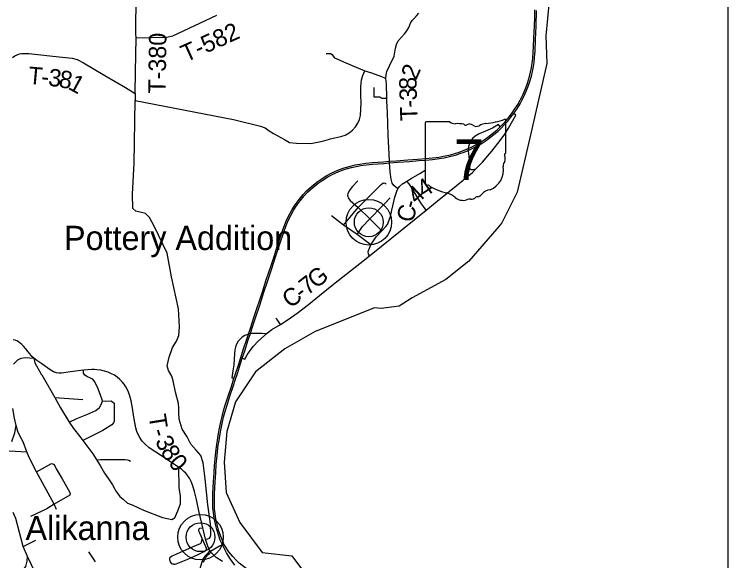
# Model space of a CAD drawing. Extents: x 2402298 to 2498138, y 789485 to 950881.
# Drawn here: x 2484526 to 2496836, y 874577 to 883995 of the extents above; entities that cross this region are included whole.
import ezdxf

# ---------------------------------------------------------------- set-up
doc = ezdxf.new("R2010")
doc.units = 0
for name, color, linetype in [('GM_X_County', 7, 'Continuous'), ('GM_X_County_Road', 7, 'Continuous'), ('GM_X_County_Road_Text', 7, 'Continuous'), ('GM_X_Interchange_Ramps', 7, 'Continuous'), ('GM_X_State_Route', 7, 'Continuous'), ('GM_X_State_Shield', 7, 'Continuous'), ('GM_X_Township', 7, 'Continuous'), ('GM_X_Township_Road', 7, 'Continuous'), ('GM_X_Township_Road_Text', 7, 'Continuous'), ('GM_X_Unincorporated', 7, 'Continuous'), ('GM_X_Unincorporated_Text', 7, 'Continuous'), ('SH_Text', 7, 'Continuous')]:
    doc.layers.add(name, color=color, linetype=linetype)

msp = doc.modelspace()

# ---------------------------------------------------------------- linework, layer by layer
at = {"layer": 'GM_X_County'}
msp.add_lwpolyline([(2493786, 884527), (2493696, 883623), (2493714, 883148), (2493437, 881943), (2493206, 880930), (2492937, 880401), (2492855, 880298), (2492372, 879737), (2491970, 879426), (2491391, 879109), (2491168, 878963), (2490858, 878924), (2490743, 878938), (2489719, 878525), (2489193, 878228), (2488688, 877835), (2488342, 877317), (2488195, 876804), (2488146, 876274), (2488182, 875754), (2488416, 875238), (2488804, 874720), (2489314, 874658), (2489689, 874158)], dxfattribs=at)
at = {"layer": 'GM_X_County_Road'}
for points in [[(2491237, 881079), (2491301, 881119), (2491373, 881162), (2491526, 881251), (2491618, 881307)], [(2488871, 878489), (2488973, 878560), (2489117, 878650), (2489235, 878722), (2489410, 878841), (2489600, 878990), (2489794, 879147), (2490037, 879345), (2490491, 879697), (2490658, 879833), (2491632, 880617), (2491825, 880776), (2492030, 880942), (2492270, 881138), (2492309, 881177), (2492339, 881221)], [(2490658, 879833), (2490637, 879861), (2490631, 879907), (2490679, 880023), (2490772, 880157), (2490870, 880265), (2490940, 880337), (2490964, 880369), (2490978, 880401), (2491015, 880509), (2491043, 880616), (2491090, 880843), (2491126, 880945), (2491146, 880986), (2491173, 881024), (2491233, 881077), (2491237, 881079)], [(2488120, 874563), (2488012, 874634), (2487946, 874695), (2487920, 874726), (2487913, 874734)]]:
    msp.add_lwpolyline(points, dxfattribs=at)
at = {"layer": 'GM_X_Interchange_Ramps'}
for points in [[(2492339, 881221), (2492370, 881219), (2492430, 881270), (2492478, 881320), (2492603, 881445), (2492698, 881553), (2492768, 881636), (2492911, 881820), (2492988, 881926), (2493053, 882033), (2493127, 882165), (2493179, 882259), (2493144, 882284)], [(2492911, 882058), (2492884, 882093), (2492779, 882035), (2492655, 881981), (2492546, 881933), (2492478, 881894), (2492434, 881853), (2492399, 881808), (2492378, 881762), (2492366, 881717), (2492359, 881682), (2492358, 881650), (2492362, 881590), (2492368, 881543), (2492382, 881443), (2492385, 881392), (2492380, 881345), (2492377, 881322), (2492372, 881300), (2492362, 881272), (2492348, 881241), (2492339, 881221)], [(2492380, 881345), (2492395, 881329), (2492404, 881321), (2492424, 881317), (2492445, 881319), (2492467, 881328), (2492478, 881320)], [(2488871, 878489), (2488805, 878493), (2488642, 878493), (2488601, 878491), (2488568, 878484), (2488503, 878460), (2488457, 878431), (2488422, 878398), (2488391, 878358), (2488363, 878308), (2488345, 878258), (2488334, 878212), (2488326, 878147), (2488312, 877955), (2488299, 877850), (2488278, 877731), (2488316, 877716)], [(2488461, 878069), (2488502, 878053), (2488544, 878125), (2488583, 878184), (2488647, 878268), (2488738, 878366), (2488840, 878453), (2488871, 878489)], [(2487901, 874750), (2487886, 874731), (2487868, 874708), (2487846, 874690), (2487825, 874669), (2487803, 874638), (2487782, 874601), (2487762, 874553), (2487721, 874420), (2487707, 874379), (2487675, 874290), (2487640, 874219), (2487598, 874147), (2487544, 874073), (2487499, 874019), (2487462, 873981), (2487487, 873946)], [(2487789, 874549), (2487806, 874590), (2487824, 874624), (2487841, 874650), (2487864, 874676), (2487901, 874708), (2487920, 874726)]]:
    msp.add_lwpolyline(points, dxfattribs=at)
at = {"layer": 'GM_X_State_Route'}
msp.add_line((2487913, 874734), (2487901, 874750), dxfattribs=at)
for points in [[(2488331, 874497), (2488256, 874603), (2488189, 874712), (2488117, 874849), (2488080, 874931), (2488054, 875004), (2488022, 875112), (2487998, 875206), (2487976, 875314), (2487964, 875399), (2487954, 875485), (2487952, 875620), (2487954, 875741), (2487966, 875937), (2487975, 876098), (2487983, 876218), (2487992, 876335), (2488004, 876453), (2488019, 876580), (2488049, 876772), (2488066, 876864), (2488090, 876970), (2488113, 877061), (2488138, 877161), (2488161, 877240), (2488223, 877430), (2488272, 877582), (2488316, 877716), (2488350, 877817), (2488387, 877930), (2488435, 878080), (2488484, 878228), (2488533, 878378), (2488568, 878484), (2488601, 878583), (2488662, 878771), (2488712, 878923), (2488762, 879074), (2488813, 879228), (2488874, 879416), (2488913, 879535), (2488963, 879685), (2489014, 879839), (2489062, 879990), (2489100, 880105), (2489153, 880260), (2489195, 880373), (2489226, 880447), (2489278, 880556), (2489319, 880628), (2489359, 880691), (2489391, 880736), (2489439, 880802), (2489513, 880890), (2489571, 880951), (2489652, 881026), (2489745, 881101), (2489819, 881154), (2489918, 881215), (2489993, 881254), (2490060, 881287), (2490137, 881319), (2490218, 881349), (2490326, 881380), (2490407, 881398), (2490491, 881413), (2490592, 881427), (2490703, 881438), (2490898, 881453), (2491001, 881461), (2491117, 881470), (2491315, 881486), (2491486, 881499), (2491629, 881511), (2491740, 881521), (2491851, 881535), (2491933, 881549), (2492051, 881574), (2492129, 881596), (2492202, 881619), (2492277, 881647), (2492359, 881682), (2492422, 881711), (2492493, 881749), (2492562, 881788), (2492631, 881832), (2492699, 881878), (2492777, 881938), (2492856, 882006), (2492911, 882058), (2492962, 882108), (2493016, 882167), (2493071, 882234), (2493119, 882298), (2493153, 882346), (2493214, 882443), (2493255, 882515), (2493308, 882620), (2493354, 882730), (2493383, 882809), (2493417, 882920), (2493435, 882997), (2493451, 883075), (2493464, 883153), (2493473, 883235), (2493482, 883350), (2493487, 883434), (2493493, 883591), (2493500, 883790), (2493506, 883946), (2493510, 884073)], [(2492358, 881650), (2492439, 881688), (2492511, 881726), (2492580, 881765), (2492649, 881809), (2492714, 881855), (2492779, 881904), (2492873, 881983), (2492928, 882035), (2492987, 882094), (2493040, 882153), (2493095, 882220), (2493144, 882284), (2493208, 882379), (2493253, 882454), (2493291, 882521), (2493342, 882627), (2493387, 882737), (2493421, 882834), (2493448, 882929), (2493467, 883008), (2493483, 883096), (2493494, 883166), (2493504, 883254), (2493512, 883362), (2493519, 883558), (2493529, 883788), (2493539, 884061)], [(2488053, 876612), (2488077, 876766), (2488095, 876858), (2488119, 876969), (2488138, 877052), (2488165, 877150), (2488191, 877241), (2488252, 877430), (2488301, 877577), (2488342, 877706), (2488376, 877806), (2488413, 877919), (2488461, 878069), (2488503, 878196), (2488564, 878382), (2488601, 878491), (2488628, 878573), (2488689, 878762), (2488762, 878983), (2488834, 879204), (2488894, 879388), (2488968, 879611), (2489041, 879834), (2489103, 880020), (2489176, 880242), (2489216, 880352), (2489254, 880442), (2489301, 880538), (2489344, 880615), (2489377, 880668), (2489408, 880713), (2489457, 880779), (2489530, 880867), (2489588, 880928), (2489677, 881010), (2489767, 881084), (2489837, 881131), (2489936, 881192), (2490010, 881231), (2490077, 881264), (2490155, 881296), (2490235, 881324), (2490346, 881356), (2490425, 881373), (2490507, 881387), (2490602, 881400), (2490709, 881410), (2490902, 881426), (2491002, 881432), (2491147, 881445), (2491344, 881460), (2491504, 881473), (2491625, 881482), (2491743, 881494), (2491825, 881503), (2491942, 881522), (2492059, 881548), (2492138, 881569), (2492215, 881594), (2492286, 881620), (2492358, 881650)], [(2485718, 877860), (2485494, 877830), (2485342, 877808), (2485296, 877808), (2485253, 877813), (2485204, 877832), (2485147, 877868), (2484999, 877969), (2484916, 878028), (2484865, 878069), (2484832, 878099), (2484793, 878142), (2484766, 878177), (2484725, 878229), (2484684, 878275), (2484658, 878303), (2484629, 878329), (2484600, 878349), (2484571, 878366), (2484540, 878377), (2484509, 878385)], [(2487794, 875096), (2487782, 875146), (2487712, 875439), (2487668, 875634), (2487637, 875769), (2487609, 875867), (2487581, 875943), (2487551, 875998), (2487521, 876042), (2487487, 876083), (2487454, 876115), (2487414, 876152), (2487367, 876186), (2487205, 876294), (2486966, 876447), (2486856, 876522), (2486778, 876591), (2486734, 876640), (2486699, 876688), (2486665, 876750), (2486642, 876805), (2486623, 876865), (2486610, 876929), (2486588, 877050), (2486566, 877205), (2486541, 877335), (2486514, 877434), (2486483, 877511), (2486451, 877574), (2486421, 877620), (2486389, 877659), (2486347, 877701), (2486301, 877740), (2486253, 877772), (2486205, 877797), (2486146, 877824), (2486085, 877845), (2486017, 877862), (2485952, 877869), (2485908, 877872), (2485863, 877872), (2485718, 877860)], [(2487980, 875567), (2487979, 875613), (2487983, 875733), (2487994, 875930), (2488003, 876089), (2488012, 876239), (2488021, 876332), (2488033, 876457), (2488047, 876571), (2488053, 876612)], [(2487983, 875465), (2487982, 875476), (2487980, 875567)], [(2488143, 874860), (2488118, 874923), (2488092, 874992), (2488052, 875104), (2488027, 875198), (2488005, 875297), (2487990, 875389), (2487983, 875465)], [(2487901, 874750), (2487886, 874783), (2487862, 874843), (2487827, 874946), (2487794, 875096)], [(2488143, 874860), (2488117, 874849), (2488068, 874828), (2487913, 874734)], [(2488295, 874650), (2488230, 874730), (2488143, 874860)], [(2488900, 874171), (2488900, 874171), (2488837, 874242), (2488731, 874307), (2488600, 874392), (2488503, 874460), (2488408, 874537), (2488350, 874590), (2488302, 874642), (2488295, 874650)]]:
    msp.add_lwpolyline(points, dxfattribs=at)
at = {"layer": 'GM_X_State_Shield'}
for p, q in [((2493010, 881614), (2493010, 882167)), ((2491618, 882123), (2491618, 881066)), ((2492039, 882141), (2491631, 882141)), ((2493010, 881615), (2493010, 881614))]:
    msp.add_line(p, q, dxfattribs=at)
for centre, radius, start, end in [((2492514, 883581), 1476, 275.8445, 288.9065), ((2492994, 882169), 15.5, 351.8621, 97.738), ((2491634, 882125), 16.1, 98.1301, 188.1301), ((2492136, 882264), 156, 231.6195, 271.1119), ((2492188, 881548), 562, 80.4867, 94.9883), ((2492316, 882130), 45.1, 219.7921, 297.1024), ((2492382, 882008), 93.8, 54.4667, 119.1411), ((2492503, 882176), 113, 233.8562, 294.8282), ((2492702, 881818), 297, 97.3462, 120.7689), ((2493006, 881574), 24, 107.944, 210.337), ((2492854, 881504), 144, 340.033, 23.6496), ((2492993, 881612), 16.6, 289.6038, 7.7341), ((2493065, 881383), 105, 136.8065, 186.9296), ((2492597, 881313), 369, 292.3089, 8.9858), ((2491634, 881064), 16.3, 171.9584, 258.3066), ((2491636, 881172), 124, 267.339, 280.6039), ((2491662, 881005), 44.8, 29.7484, 93.2717), ((2492227, 881955), 1066, 240.4129, 257.1985), ((2492752, 880769), 202, 94.4031, 142.5768), ((2491909, 880591), 334, 47.1842, 75.836), ((2492270, 881000), 212, 230.7004, 286.2918), ((2492392, 880635), 174, 85.6951, 111.2099), ((2492408, 880921), 113, 268.777, 315.5493), ((2492510, 880818), 31.8, 65.7517, 132.6484), ((2492496, 880964), 119, 282.8732, 323.2771)]:
    msp.add_arc(centre, radius, start, end, dxfattribs=at)
at = {"layer": 'GM_X_Township'}
msp.add_lwpolyline([(2493786, 884527), (2493696, 883623), (2493714, 883148), (2493437, 881943), (2493206, 880930), (2492937, 880401), (2492855, 880298), (2492372, 879737), (2491970, 879426), (2491391, 879109), (2491168, 878963), (2490858, 878924), (2490743, 878938), (2489719, 878525), (2489193, 878228), (2488688, 877835), (2488342, 877317), (2488195, 876804), (2488146, 876274), (2488182, 875754), (2488416, 875238), (2488804, 874720), (2489314, 874658), (2489689, 874158)], dxfattribs=at)
at = {"layer": 'GM_X_Township_Road'}
for p, q in [((2490206, 883177), (2490577, 883019)), ((2486611, 882628), (2486618, 883003)), ((2485224, 877392), (2485709, 877354)), ((2484441, 876468), (2484743, 876451)), ((2485078, 875465), (2484809, 875337)), ((2484682, 874823), (2484896, 874928))]:
    msp.add_line(p, q, dxfattribs=at)
for points in [[(2486626, 883661), (2486624, 883739), (2486629, 884268), (2486628, 884307), (2486614, 884331), (2486593, 884347), (2486512, 884392), (2486479, 884423), (2486450, 884467), (2486015, 885223), (2485534, 885643), (2484538, 886597), (2484648, 886904), (2484650, 886910)], [(2491156, 883542), (2491209, 883603), (2491258, 883658), (2491297, 883710), (2491334, 883769), (2491360, 883844), (2491390, 883887), (2491422, 883918), (2491466, 883968), (2491506, 884013)], [(2486629, 883591), (2487153, 883601), (2487260, 883626), (2488024, 883978)], [(2486618, 883003), (2486629, 883591), (2486626, 883661)], [(2490940, 882886), (2490945, 882950), (2490956, 883009), (2490998, 883106), (2491080, 883273), (2491093, 883341), (2491106, 883411), (2491124, 883472), (2491152, 883538), (2491156, 883542)], [(2484493, 883248), (2484537, 883280), (2484575, 883297), (2484614, 883311), (2484658, 883317), (2484698, 883319), (2484778, 883317), (2485192, 883276), (2485526, 883236), (2485612, 883213), (2485723, 883158), (2486086, 882941), (2486443, 882731), (2486611, 882628)], [(2489905, 883321), (2489984, 883318), (2490012, 883302), (2490030, 883272), (2490052, 883245), (2490123, 883213), (2490206, 883177)], [(2489964, 881842), (2489979, 881846), (2490060, 881865), (2490158, 881886), (2490234, 881913), (2490306, 881949), (2490362, 881998), (2490412, 882054), (2490452, 882116), (2490481, 882182), (2490499, 882251), (2490510, 882466), (2490507, 882595), (2490508, 882679), (2490508, 882750), (2490512, 882807), (2490518, 882864), (2490542, 882939), (2490577, 883019), (2490689, 882985), (2490861, 882923), (2490912, 882902), (2490940, 882886)], [(2491146, 880986), (2491074, 881043), (2491049, 881084), (2491030, 881151), (2491014, 881281), (2491002, 881432), (2491001, 881461), (2490994, 881582), (2490978, 881912), (2490969, 882105), (2490965, 882303), (2490955, 882500), (2490952, 882549), (2490947, 882798), (2490940, 882886)], [(2490728, 882733), (2490728, 882574), (2490766, 882574)], [(2486611, 882628), (2486611, 882577), (2486613, 882509)], [(2490766, 882574), (2490831, 882572), (2490871, 882547), (2490952, 882549)], [(2487363, 877206), (2487359, 877288), (2487306, 877480), (2487268, 877677), (2487243, 877755), (2487188, 877853), (2487164, 877936), (2487199, 878083), (2487257, 878251), (2487328, 878361), (2487364, 878459), (2487377, 878607), (2487360, 878920), (2487240, 879469), (2487165, 879880), (2486939, 880341), (2486857, 880494), (2486788, 880561), (2486624, 880600), (2486570, 880647), (2486568, 880895), (2486596, 881430), (2486613, 882509)], [(2486613, 882509), (2488308, 882180), (2488777, 882065), (2488858, 882036), (2488927, 881987), (2488999, 881940), (2489186, 881836), (2489276, 881788), (2489394, 881774), (2489645, 881766), (2489843, 881810), (2489964, 881842)], [(2490453, 881123), (2490357, 881021), (2490303, 880953), (2490284, 880902), (2490278, 880879), (2490279, 880859)], [(2490803, 881009), (2490857, 881063), (2490883, 881083), (2490896, 881087), (2490911, 881088), (2490926, 881084), (2490945, 881074)], [(2491632, 880617), (2491586, 880680), (2491550, 880730), (2491502, 880811), (2491459, 880880), (2491384, 881001), (2491341, 881071), (2491301, 881119)], [(2490209, 880362), (2490460, 880662), (2490803, 881009)], [(2490279, 880859), (2490280, 880854), (2490286, 880830), (2490298, 880812), (2490319, 880788), (2490460, 880662), (2490662, 880467), (2490870, 880265)], [(2490873, 880685), (2490908, 880720), (2491012, 880832)], [(2490443, 880201), (2490535, 880336), (2490662, 880467), (2490873, 880685)], [(2490679, 880023), (2490443, 880201), (2490209, 880362), (2490000, 880522)], [(2489117, 878650), (2489097, 878683), (2489062, 878732), (2489040, 878757)], [(2484511, 877962), (2484545, 878000), (2484586, 878040), (2484644, 878065), (2484722, 878077), (2484865, 878069)], [(2484865, 878069), (2484880, 877990), (2484992, 877792)], [(2486046, 877334), (2486010, 877450), (2485965, 877567), (2485908, 877666), (2485880, 877707), (2485792, 877747), (2485741, 877772), (2485720, 877808), (2485718, 877860)], [(2484992, 877792), (2485000, 877779), (2485224, 877392), (2485326, 877214), (2485476, 876963), (2485546, 876858), (2485655, 876715), (2485710, 876646), (2485881, 876417), (2486006, 876220), (2486084, 876086), (2486150, 875990), (2486223, 875884), (2486264, 875811), (2486287, 875770)], [(2485476, 876963), (2485607, 877030), (2485780, 877096), (2485935, 877166), (2485999, 877219), (2486030, 877280), (2486046, 877334), (2486094, 877324), (2486194, 877330), (2486223, 877317), (2486247, 877294), (2486251, 877033), (2486247, 876982), (2486237, 876953), (2486212, 876921), (2486053, 876820), (2485710, 876646)], [(2484485, 876630), (2484535, 876779), (2484557, 876905), (2484533, 877034), (2484501, 877199)], [(2487827, 874946), (2487867, 874953), (2487892, 874967), (2487909, 874982), (2487914, 874998), (2487915, 875015), (2487912, 875213), (2487866, 875540), (2487819, 875986), (2487785, 876266), (2487747, 876392), (2487662, 876480), (2487571, 876584), (2487508, 876710), (2487423, 876842), (2487373, 877015), (2487366, 877135), (2487363, 877206)], [(2485253, 875460), (2485215, 875549), (2484907, 876107), (2484783, 876356), (2484743, 876451), (2484678, 876623), (2484629, 876719), (2484590, 876802), (2484557, 876905)], [(2484907, 876107), (2485167, 876252), (2485201, 876239), (2485227, 876210), (2485249, 876158), (2485350, 875988), (2485479, 875762), (2485488, 875734), (2485485, 875706), (2485215, 875549), (2485089, 875471), (2485078, 875465)], [(2485944, 876318), (2486012, 876319), (2486119, 876319), (2486373, 876321), (2486438, 876320), (2486480, 876316), (2486505, 876308), (2486534, 876293)], [(2487271, 875303), (2487299, 875317), (2487351, 875434), (2487395, 875559), (2487392, 875691), (2487370, 875837), (2487367, 876186)], [(2486287, 875770), (2486300, 875748), (2486347, 875685), (2486403, 875637), (2486478, 875569), (2486558, 875538), (2486756, 875448), (2487081, 875321), (2487242, 875288), (2487271, 875303)], [(2484962, 874217), (2484756, 874650), (2484682, 874823), (2484554, 875304), (2484505, 875407)], [(2487845, 874785), (2487830, 874815), (2487767, 874961), (2487710, 875092), (2487710, 875118), (2487729, 875135), (2487782, 875146)], [(2487221, 874644), (2487248, 874660), (2487277, 874672), (2487384, 874718), (2487602, 874818), (2487738, 874873), (2487750, 874883), (2487758, 874895), (2487764, 874924), (2487767, 874961)], [(2487277, 874515), (2487300, 874518), (2487320, 874524), (2487375, 874547), (2487523, 874605), (2487697, 874681), (2487801, 874733), (2487835, 874761), (2487845, 874785)], [(2484480, 874046), (2484486, 874162), (2484506, 874235), (2484562, 874311), (2484658, 874388), (2484723, 874478), (2484750, 874567), (2484756, 874650)], [(2485928, 874559), (2485815, 874727)], [(2487277, 874515), (2487260, 874518), (2487246, 874525), (2487233, 874540), (2487224, 874557), (2487213, 874591), (2487210, 874621), (2487214, 874635), (2487221, 874644)]]:
    msp.add_lwpolyline(points, dxfattribs=at)
at = {"layer": 'GM_X_Unincorporated'}
for centre, radius in [((2490643, 880411), 393), ((2490643, 880411), 249), ((2487739, 874982), 393), ((2487739, 874982), 249)]:
    msp.add_circle(centre, radius, dxfattribs=at)
at = {"layer": 'SH_Text'}
msp.add_lwpolyline([(2448187, 889729), (2496836, 889729), (2496836, 859271), (2448187, 859271)], close=True, dxfattribs=at)

# ---------------------------------------------------------------- texts
at = {"layer": 'GM_X_County_Road_Text'}
for s, rotation, p in [('4', 33.3056, (2491596, 880825)), ('4', 42.8256, (2491472, 880708)), ('C', 77.0088, (2491409, 880393)), ('-', 74.7437, (2491463, 880628)), ('G', 37.797, (2489730, 879254)), ('7', 37.7939, (2489585, 879142)), ('C', 36.8675, (2489288, 878917)), ('-', 37.7771, (2489488, 879067))]:
    msp.add_text(s, height=300, rotation=rotation, dxfattribs=at).set_placement(p)
at = {"layer": 'GM_X_State_Shield'}
msp.add_text('7', height=696, dxfattribs=at).set_placement((2492114, 881141))
at = {"layer": 'GM_X_Township_Road_Text'}
for s, rotation, p in [('T-582', 24.3044, (2487487, 883162)), ('T-380', 89.1579, (2487137, 882626)), ('2', 66.6483, (2491461, 882848)), ('T', 354.7602, (2484757, 882797)), ('3', 353.2455, (2485101, 882765)), ('8', 349.381, (2485279, 882744)), ('-', 354.3865, (2484980, 882777)), ('1', 331.3958, (2485437, 882718)), ('8', 90.6297, (2491469, 882695)), ('3', 91.9884, (2491476, 882512)), ('-', 92.073, (2491480, 882389)), ('T', 92.0618, (2491488, 882165)), ('T', 278.9762, (2486843, 877078)), ('3', 297.6848, (2486948, 876638)), ('-', 287.0173, (2486888, 876812)), ('8', 301.0853, (2487043, 876458)), ('0', 310.6984, (2487170, 876255))]:
    msp.add_text(s, height=300, rotation=rotation, dxfattribs=at).set_placement(p)
at = {"layer": 'GM_X_Unincorporated_Text'}
for s, p in [('Pottery Addition', (2485385, 879932)), ('Alikanna', (2484720, 874933))]:
    msp.add_text(s, height=417, rotation=0, dxfattribs=at).set_placement(p)

doc.saveas('drawing.dxf')
